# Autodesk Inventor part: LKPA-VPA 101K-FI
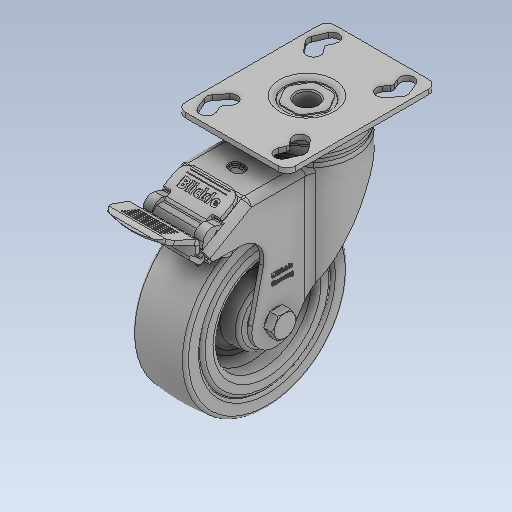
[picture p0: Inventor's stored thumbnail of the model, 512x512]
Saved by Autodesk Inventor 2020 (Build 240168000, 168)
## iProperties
Created: 1900-01
Part Number: LKPA-VPA 101K-FI
Material: Générique
Document SubType Name: Modeling
Designer: bruno
Density: 1 g/cm^3
Appearance: Par défaut
Author: bruno
Revision Number: ANYUNSPECIFIED
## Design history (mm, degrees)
feature "Base1"
feature "Base2"
feature "Base3"
feature "Base4"
node "Solide1"
node "Solide2"
node "Solide3"
node "Solide4"
